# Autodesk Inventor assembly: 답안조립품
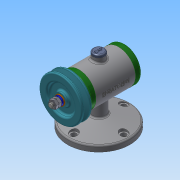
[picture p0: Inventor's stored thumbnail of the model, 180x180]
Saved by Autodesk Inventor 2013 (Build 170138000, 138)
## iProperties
Created: 2018-12
Part Number: 답안조립품
Document SubType Name: Assembly
Designer: Gpr
Author: Gpr
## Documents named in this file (15)
- C:\Users\Administrator\Desktop\481207V1037\답안조립품.iam
- C:\Users\Administrator\Desktop\481207V1037\본체.ipt
- C:\Users\Administrator\Desktop\481207V1037\뒤커버.ipt
- C:\Users\Administrator\Desktop\481207V1037\베어링 15 x 32 x 9.ipt
- C:\Users\Administrator\Desktop\481207V1037\축.ipt
- C:\Users\Administrator\Desktop\481207V1037\볼트 M4 x 12.ipt
- C:\Users\Administrator\Desktop\481207V1037\앞커버.ipt
- C:\Users\Administrator\Desktop\481207V1037\오일 실 15 25 7.ipt
- C:\Users\Administrator\Desktop\481207V1037\키 3 x 3 x 12.ipt
- C:\Users\Administrator\Desktop\481207V1037\V벨트풀리.ipt
- C:\Users\Administrator\Desktop\481207V1037\고무캡.ipt
- C:\Users\Administrator\Desktop\481207V1037\너트 M8.ipt
- 너트 M8.ipt
- C:\Users\Administrator\Desktop\481207V1037\스프링와셔 8.ipt
- C:\Users\Administrator\Desktop\481207V1037\와셔 8x17.ipt
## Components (2 placed, 2 different names)
1. V벨트풀리:1
2. 고무캡:1
